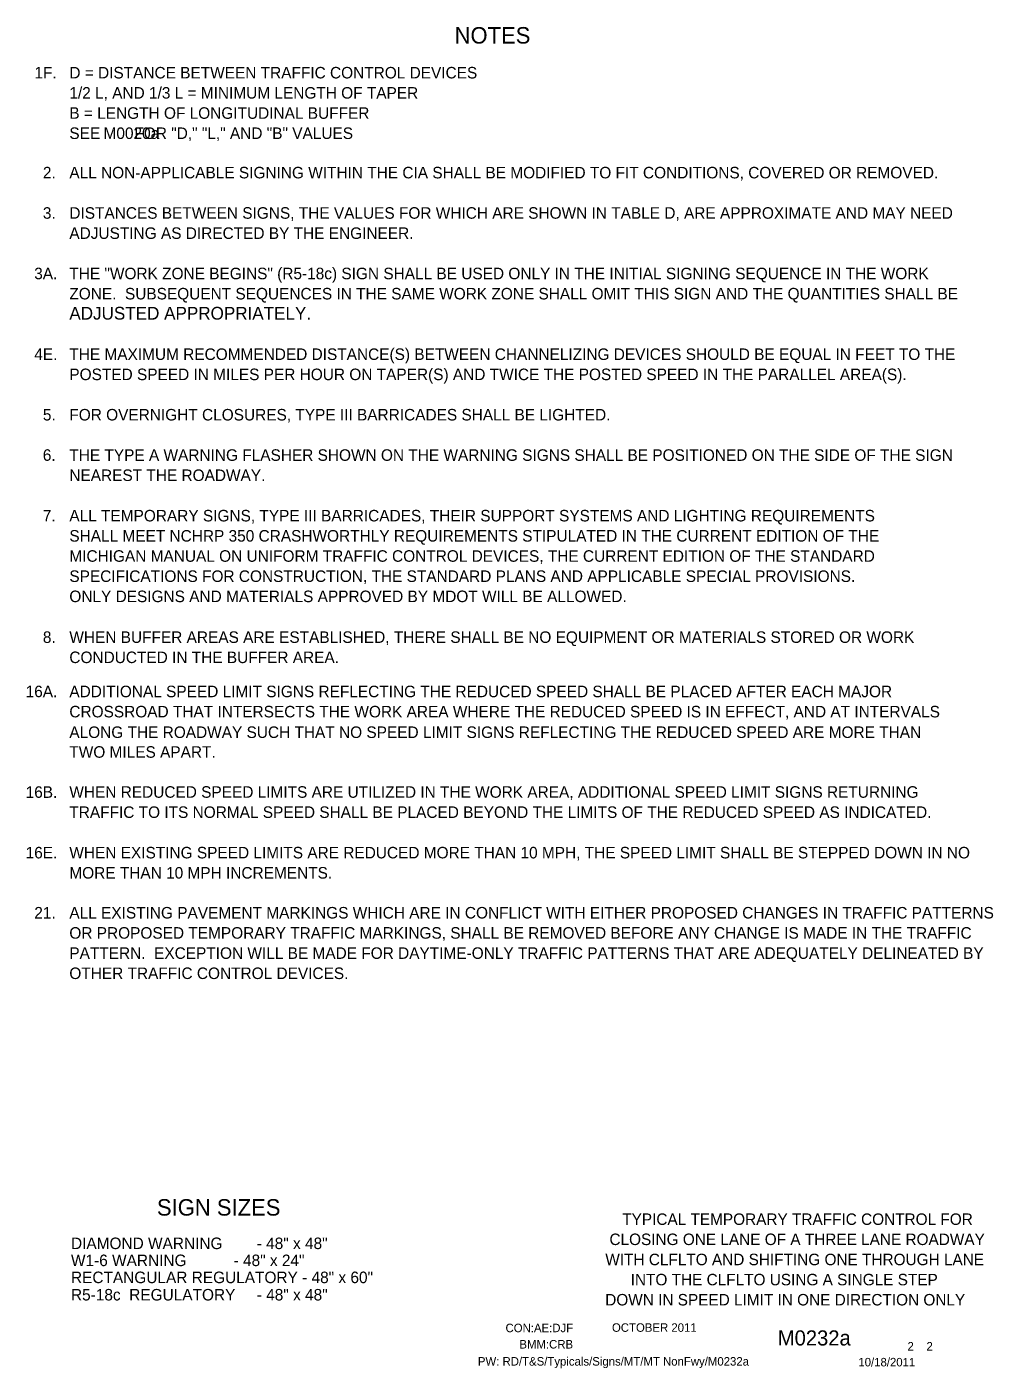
# Model space of a CAD drawing. Extents: x 16750 to 18296, y 5932 to 6919.
# Drawn here: x 17592 to 18296, y 5932 to 6909 of the extents above; entities that cross this region are included whole.
import ezdxf

# ---------------------------------------------------------------- set-up
doc = ezdxf.new("R2010")
doc.units = 0
for name, color, linetype in [('BORDER', 7, 'Continuous'), ('BORDER_SIGNAL_WO', 7, 'Continuous'), ('TYPICAL_TEXT_DIMEN_EX', 7, 'Continuous')]:
    doc.layers.add(name, color=color, linetype=linetype)

msp = doc.modelspace()

# ---------------------------------------------------------------- linework, layer by layer
at = {"layer": 'BORDER'}
msp.add_line((17753.49, 6055), (17753.49, 6055), dxfattribs=at)

# ---------------------------------------------------------------- texts
at = {"layer": 'BORDER_SIGNAL_WO'}
for s, height, p in [('TYPICAL TEMPORARY TRAFFIC CONTROL FOR', 8.37, (18025.78, 6036.21)), ('CLOSING ONE LANE OF A THREE LANE ROADWAY', 8.37, (18016.47, 6021.54)), ('WITH CLFLTO AND SHIFTING ONE THROUGH LANE', 8.37, (18013.45, 6006.87)), ('INTO THE CLFLTO USING A SINGLE STEP', 8.37, (18031.95, 5992.2)), ('DOWN IN SPEED LIMIT IN ONE DIRECTION ONLY', 8.37, (18013.38, 5977.53)), ('CON:AE:DJF  ', 6.2, (17940.69, 5958.06)), ('    OCTOBER 2011    ', 6.2, (18009.08, 5958.34)), ('BMM:CRB   ', 6.2, (17950.81, 5946.17)), ('    M0232a   ', 11, (18122.86, 5948.38)), (' 2    2 ', 6.2, (18231.45, 5944.7)), ('PW: RD/T&S/Typicals/Signs/MT/MT NonFwy/M0232a  ', 6.2, (17920.55, 5933.71)), ('10/18/2011    ', 6.2, (18197.93, 5933.13))]:
    msp.add_text(s, height=height, dxfattribs=at).set_placement(p)
at = {"layer": 'TYPICAL_TEXT_DIMEN_EX'}
for s, height, p in [('NOTES', 12, (17903.55, 6897)), ('1F.', 8.4, (17597.19, 6871.56)), ('D = DISTANCE BETWEEN TRAFFIC CONTROL DEVICES', 8.4, (17622.7, 6871.56)), ('1/2 L, AND 1/3 L = MINIMUM LENGTH OF TAPER', 8.4, (17622.7, 6856.86)), ('B = LENGTH OF LONGITUDINAL BUFFER', 8.4, (17622.7, 6842.16)), ('SEE        FOR "D," "L," AND "B" VALUES', 8.4, (17622.7, 6827.46)), ('M0020a', 8.4, (17647.62, 6827.46)), ('2.', 8.4, (17603.39, 6798.75)), ('ALL NON-APPLICABLE SIGNING WITHIN THE CIA SHALL BE MODIFIED TO FIT CONDITIONS, COVERED OR REMOVED.', 8.4, (17622.7, 6798.75)), ('3.', 8.4, (17603.39, 6769.35)), ('DISTANCES BETWEEN SIGNS, THE VALUES FOR WHICH ARE SHOWN IN TABLE D, ARE APPROXIMATE AND MAY NEED', 8.4, (17622.7, 6769.35)), ('ADJUSTING AS DIRECTED BY THE ENGINEER.', 8.4, (17622.7, 6754.65)), ('THE "WORK ZONE BEGINS" (R5-18c) SIGN SHALL BE USED ONLY IN THE INITIAL SIGNING SEQUENCE IN THE WORK', 8.4, (17622.7, 6725.25)), ('3A.', 8.4, (17597.09, 6725.25)), ('ZONE.  SUBSEQUENT SEQUENCES IN THE SAME WORK ZONE SHALL OMIT THIS SIGN AND THE QUANTITIES SHALL BE', 8.4, (17622.7, 6710.55)), ('ADJUSTED APPROPRIATELY.', 9.3, (17622.7, 6695.85)), ('THE MAXIMUM RECOMMENDED DISTANCE(S) BETWEEN CHANNELIZING DEVICES SHOULD BE EQUAL IN FEET TO THE', 8.4, (17622.7, 6666.45)), ('4E.', 8.4, (17597.13, 6666.45)), ('POSTED SPEED IN MILES PER HOUR ON TAPER(S) AND TWICE THE POSTED SPEED IN THE PARALLEL AREA(S).', 8.4, (17622.7, 6651.75)), ('5.', 8.4, (17603.39, 6622.35)), ('FOR OVERNIGHT CLOSURES, TYPE III BARRICADES SHALL BE LIGHTED.', 8.4, (17622.7, 6622.35)), ('6.', 8.4, (17603.34, 6592.95)), ('THE TYPE A WARNING FLASHER SHOWN ON THE WARNING SIGNS SHALL BE POSITIONED ON THE SIDE OF THE SIGN', 8.4, (17622.7, 6592.95)), ('NEAREST THE ROADWAY.', 8.4, (17622.7, 6578.25)), ('7.', 8.4, (17603.34, 6548.78)), ('ALL TEMPORARY SIGNS, TYPE III BARRICADES, THEIR SUPPORT SYSTEMS AND LIGHTING REQUIREMENTS', 8.4, (17622.7, 6548.8)), ('SHALL MEET NCHRP 350 CRASHWORTHLY REQUIREMENTS STIPULATED IN THE CURRENT EDITION OF THE', 8.4, (17622.7, 6534.1)), ('MICHIGAN MANUAL ON UNIFORM TRAFFIC CONTROL DEVICES, THE CURRENT EDITION OF THE STANDARD', 8.4, (17622.7, 6519.4)), ('SPECIFICATIONS FOR CONSTRUCTION, THE STANDARD PLANS AND APPLICABLE SPECIAL PROVISIONS.', 8.4, (17622.7, 6504.7)), ('ONLY DESIGNS AND MATERIALS APPROVED BY MDOT WILL BE ALLOWED.', 8.4, (17622.7, 6490)), ('8.', 8.4, (17603.39, 6460.28)), ('WHEN BUFFER AREAS ARE ESTABLISHED, THERE SHALL BE NO EQUIPMENT OR MATERIALS STORED OR WORK     ', 8.4, (17622.7, 6460.28)), ('CONDUCTED IN THE BUFFER AREA.', 8.4, (17622.7, 6445.58)), ('16A.', 8.4, (17590.83, 6420.72)), ('ADDITIONAL SPEED LIMIT SIGNS REFLECTING THE REDUCED SPEED SHALL BE PLACED AFTER EACH MAJOR', 8.4, (17622.7, 6420.72)), ('CROSSROAD THAT INTERSECTS THE WORK AREA WHERE THE REDUCED SPEED IS IN EFFECT, AND AT INTERVALS', 8.4, (17622.7, 6406.02)), ('ALONG THE ROADWAY SUCH THAT NO SPEED LIMIT SIGNS REFLECTING THE REDUCED SPEED ARE MORE THAN', 8.4, (17622.7, 6391.02)), ('TWO MILES APART.', 8.4, (17622.7, 6376.62)), ('16B.', 8.4, (17590.84, 6347.4)), ('WHEN REDUCED SPEED LIMITS ARE UTILIZED IN THE WORK AREA, ADDITIONAL SPEED LIMIT SIGNS RETURNING', 8.4, (17622.7, 6347.46)), ('TRAFFIC TO ITS NORMAL SPEED SHALL BE PLACED BEYOND THE LIMITS OF THE REDUCED SPEED AS INDICATED.', 8.4, (17622.7, 6332.76)), ('16E.', 8.4, (17590.84, 6303.27)), ('WHEN EXISTING SPEED LIMITS ARE REDUCED MORE THAN 10 MPH, THE SPEED LIMIT SHALL BE STEPPED DOWN IN NO', 8.4, (17622.7, 6303.27)), ('MORE THAN 10 MPH INCREMENTS.', 8.4, (17622.7, 6288.57)), ('21.', 8.4, (17597.14, 6259.48)), ('ALL EXISTING PAVEMENT MARKINGS WHICH ARE IN CONFLICT WITH EITHER PROPOSED CHANGES IN TRAFFIC PATTERNS', 8.4, (17622.7, 6259.48)), ('OR PROPOSED TEMPORARY TRAFFIC MARKINGS, SHALL BE REMOVED BEFORE ANY CHANGE IS MADE IN THE TRAFFIC', 8.4, (17622.7, 6244.78)), ('PATTERN.  EXCEPTION WILL BE MADE FOR DAYTIME-ONLY TRAFFIC PATTERNS THAT ARE ADEQUATELY DELINEATED BY', 8.4, (17622.7, 6230.08)), ('OTHER TRAFFIC CONTROL DEVICES.', 8.4, (17622.7, 6215.38)), ('SIGN SIZES', 12, (17686.54, 6043)), ('DIAMOND WARNING        - 48" x 48"', 8.4, (17623.89, 6018.6)), ('W1-6 WARNING           - 48" x 24"', 8.4, (17623.89, 6006.2)), ('RECTANGULAR REGULATORY - 48" x 60"', 8.4, (17623.89, 5993.8)), ('R5-18c  REGULATORY     - 48" x 48"', 8.4, (17623.89, 5981.15))]:
    msp.add_text(s, height=height, dxfattribs=at).set_placement(p)

doc.saveas('drawing.dxf')
